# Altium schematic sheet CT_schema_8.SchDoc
size 226 x 144 mm
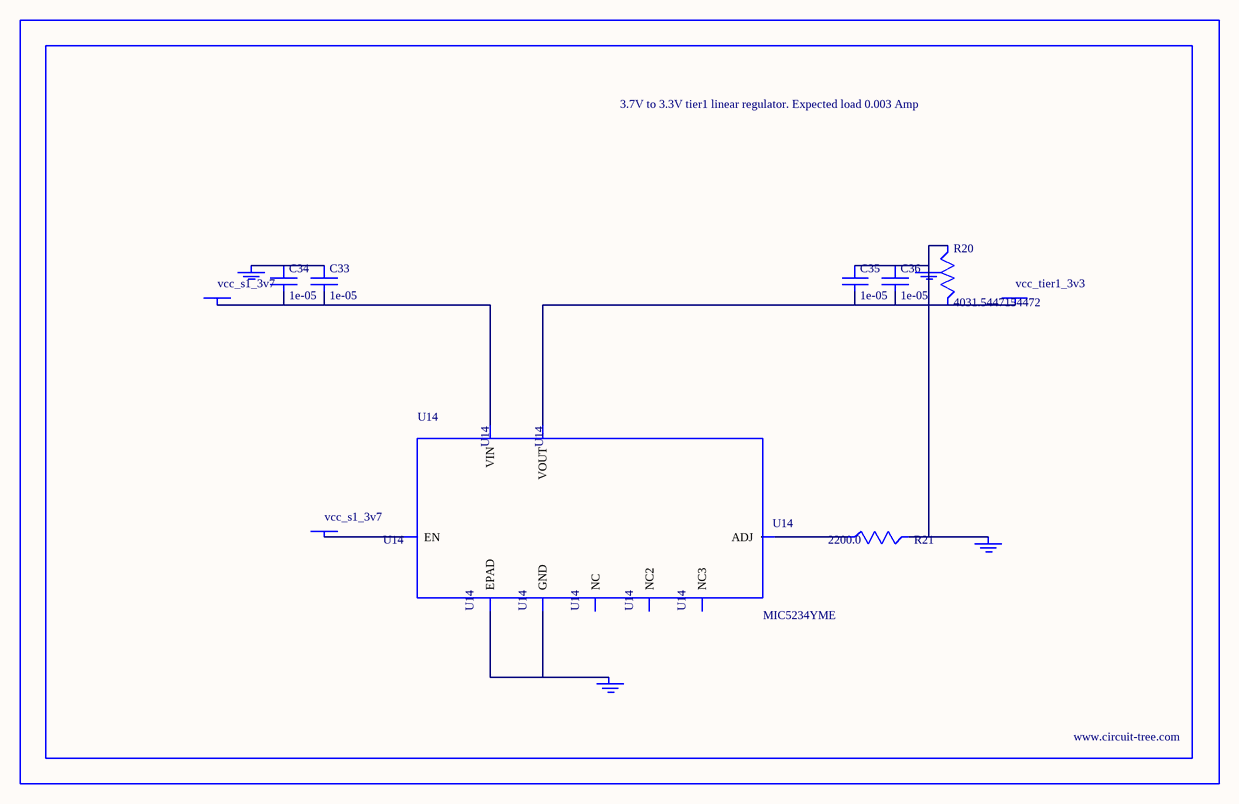
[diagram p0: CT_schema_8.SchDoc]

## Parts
BORDER7  (no value)
C33  1e-05  [C1210]
C34  1e-05  [C1210]
C35  1e-05  [C1210]
C36  1e-05  [C1210]
GND_INSTANCE_7_0  (no value)
GND_INSTANCE_7_1  (no value)
GND_INSTANCE_7_2  (no value)
GND_INSTANCE_7_3  (no value)
POWER_INSTANCE_7_0  vcc_tier1_3v3
POWER_INSTANCE_7_1  vcc_s1_3v7
POWER_INSTANCE_7_2  vcc_s1_3v7
R20  4031.5447154472  [R0603]
R21  2200.0  [R0603]
U14  MIC5234YME  [SOIC-8_EP]

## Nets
NetC33_1: C33.1 C34.1 GND_INSTANCE_7_3.0(GND)
NetC33_2: C33.2 C34.2 POWER_INSTANCE_7_2.0(PWR) U14.8(VIN)
NetC35_1: C35.1 C36.1 GND_INSTANCE_7_0.0(GND) GND_INSTANCE_7_1.0(GND) R20.1 R21.2
NetC35_2: C35.2 C36.2 POWER_INSTANCE_7_0.0(PWR) R20.2 U14.1(VOUT)
NetGND_INSTANCE_7_2_0: GND_INSTANCE_7_2.0(GND) U14.7(GND) U14.EPAD
NetPOWER_INSTANCE_7_1_0: POWER_INSTANCE_7_1.0(PWR) U14.5(EN)
NetR21_1: R21.1 U14.4(ADJ)

Not connected (* = marked no-connect by the designer): U14 2(NC) 3(NC2) 6(NC3)

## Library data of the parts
BORDER7 = BORDER_PAGE7
C33-C36 = C1210C106K5PACTU
GND_INSTANCE_7_0-GND_INSTANCE_7_3 = GND
POWER_INSTANCE_7_0-POWER_INSTANCE_7_2 = PWR
R20 = R20
R21 = RC0603JR-072K2L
